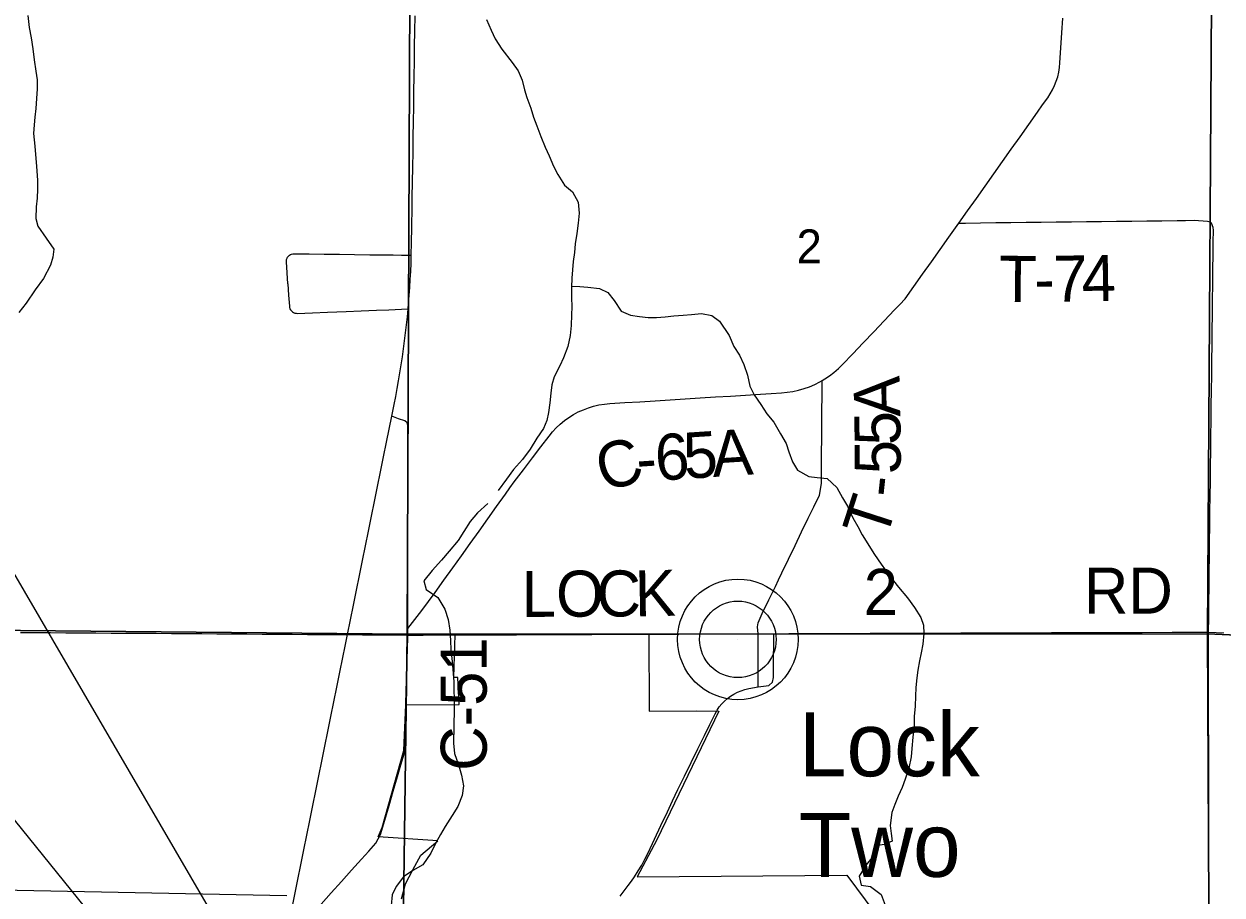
# Model space of a CAD drawing. Extents: x 0 to 34, y 0 to 22.
# Drawn here: x 5.324 to 6.802, y 18.119 to 19.194 of the extents above; entities that cross this region are included whole.
import ezdxf

# ---------------------------------------------------------------- set-up
doc = ezdxf.new("R2010")
doc.units = 0
for name, color, linetype in [('GM_X_Corporation', 7, 'Continuous'), ('GM_X_County_Road', 7, 'Continuous'), ('GM_X_County_Road_Text', 7, 'Continuous'), ('GM_X_Minor_River', 7, 'Continuous'), ('GM_X_Section_Text', 7, 'Continuous'), ('GM_X_State_Route', 7, 'Continuous'), ('GM_X_Township_Road', 7, 'Continuous'), ('GM_X_Township_Road_Text', 7, 'Continuous'), ('GM_X_Unincorporated', 7, 'Continuous'), ('GM_X_Unincorporated_Location', 7, 'Continuous'), ('GM_X_Unincorporated_Text', 7, 'Continuous'), ('SH_Text', 7, 'Continuous')]:
    doc.layers.add(name, color=color, linetype=linetype)

msp = doc.modelspace()

# ---------------------------------------------------------------- linework, layer by layer
at = {"layer": 'GM_X_Corporation'}
for points in [[(5.8008, 19.4289), (5.7966, 18.4409), (4.7982, 18.4503), (4.8082, 19.4446)], [(5.8008, 19.4289), (6.7907, 19.4159), (6.7843, 18.4413), (5.7966, 18.4409)], [(6.7967, 19.4154), (7.8071, 19.3973), (7.7914, 18.4475), (7.7907, 18.396), (6.7843, 18.4413), (6.7907, 19.4159)], [(5.7966, 18.4409), (5.7831, 17.4286), (4.7862, 17.4375), (4.7982, 18.4503)], [(5.7966, 18.4409), (6.7843, 18.4413), (6.7891, 17.4339), (5.7831, 17.4286)], [(7.7907, 18.396), (7.7756, 17.4406), (7.775, 17.3902), (6.7891, 17.4339), (6.7843, 18.4413)]]:
    msp.add_lwpolyline(points, close=True, dxfattribs=at)
for points in [[(5.7896, 18.1144), (5.7946, 18.133), (5.8037, 18.1501), (5.8135, 18.1683), (5.8344, 18.186), (5.761, 18.1909), (5.7658, 18.2026), (5.7926, 18.2977), (5.7951, 18.354), (5.7959, 18.354), (5.8607, 18.3543), (5.8593, 18.3874), (5.8544, 18.3874), (5.856, 18.4404), (6.095, 18.4413), (6.0953, 18.3461), (6.1536, 18.3463), (6.1813, 18.3461), (6.1047, 18.1874), (6.0806, 18.1418), (6.3391, 18.1436), (6.4654, 17.9737)], [(5.2945, 18.1254), (5.6481, 18.1185)]]:
    msp.add_lwpolyline(points, dxfattribs=at)
at = {"layer": 'GM_X_County_Road'}
msp.add_line((5.7977, 18.4399), (5.7977, 18.4479), dxfattribs=at)
for points in [[(6.4775, 18.9482), (6.4883, 18.9635), (6.4991, 18.9787), (6.5098, 18.9939), (6.5206, 19.0091), (6.5314, 19.0243), (6.5422, 19.0395), (6.553, 19.0547), (6.5637, 19.0699), (6.5745, 19.0851), (6.5808, 19.094), (6.5871, 19.1029), (6.5903, 19.1077), (6.5931, 19.1128), (6.5956, 19.118), (6.5977, 19.1234), (6.5995, 19.1289), (6.6008, 19.1345), (6.6018, 19.1403), (6.6023, 19.146), (6.6035, 19.1646), (6.6047, 19.1828), (6.6058, 19.2009)], [(5.7977, 18.4479), (5.8033, 18.4554), (5.8146, 18.4702), (5.8229, 18.4813), (5.8313, 18.4924), (5.8421, 18.5075), (5.853, 18.5227), (5.8638, 18.5379), (5.8746, 18.553), (5.8855, 18.5682), (5.8963, 18.5834), (5.9071, 18.5985), (5.918, 18.6137), (5.9234, 18.6214), (5.9289, 18.6291), (5.9402, 18.6439), (5.9515, 18.6587), (5.9616, 18.6721), (5.9718, 18.6855), (5.9761, 18.6907), (5.9807, 18.6956), (5.9856, 18.7003), (5.9908, 18.7046), (5.9962, 18.7085), (6.002, 18.7121), (6.0079, 18.7153), (6.0141, 18.718), (6.0204, 18.7204), (6.0268, 18.7224), (6.0334, 18.7239), (6.0401, 18.725), (6.0468, 18.7256), (6.0654, 18.7268), (6.084, 18.7279), (6.1026, 18.7291), (6.1212, 18.7302), (6.1398, 18.7314), (6.1584, 18.7325), (6.177, 18.7337), (6.1956, 18.7349), (6.2142, 18.736), (6.2328, 18.7372), (6.2458, 18.738), (6.2588, 18.7388), (6.2658, 18.7395), (6.2728, 18.7405), (6.2797, 18.7421), (6.2864, 18.744), (6.2931, 18.7464), (6.2996, 18.7492), (6.3059, 18.7523), (6.3088, 18.754), (6.312, 18.7559), (6.3178, 18.7598), (6.3234, 18.7641), (6.3288, 18.7687), (6.3338, 18.7737), (6.3467, 18.7871), (6.3595, 18.8006), (6.3724, 18.8141), (6.3853, 18.8276), (6.3982, 18.8411), (6.4047, 18.8479), (6.4112, 18.8547), (6.422, 18.8699), (6.4328, 18.8852), (6.4436, 18.9004), (6.4543, 18.9156), (6.4651, 18.9308), (6.4713, 18.9395), (6.4775, 18.9482)], [(5.7977, 18.4479), (5.7977, 18.6988), (5.7966, 18.7018), (5.7939, 18.7041), (5.7861, 18.7069), (5.7776, 18.71)], [(5.3194, 18.4432), (5.338, 18.443), (5.3567, 18.4429), (5.3753, 18.4428), (5.3939, 18.4427), (5.4126, 18.4426), (5.4312, 18.4424), (5.4499, 18.4423), (5.4685, 18.4422), (5.4871, 18.4421), (5.5058, 18.4419), (5.5244, 18.4418), (5.5431, 18.4417), (5.5617, 18.4416), (5.5804, 18.4414), (5.599, 18.4413), (5.6176, 18.4412), (5.6363, 18.441), (5.6549, 18.4409), (5.6736, 18.4408), (5.6922, 18.4407), (5.7075, 18.4406), (5.7229, 18.4405)], [(5.7229, 18.4405), (5.7415, 18.4403), (5.7602, 18.4402), (5.7788, 18.4401), (5.7977, 18.4399)], [(5.795, 18.3536), (5.7956, 18.3723), (5.7962, 18.3909), (5.7967, 18.4095), (5.7972, 18.4232), (5.7976, 18.4369), (5.7977, 18.4399)], [(5.7977, 18.4399), (5.8163, 18.44), (5.835, 18.4401), (5.8569, 18.4402)], [(5.8569, 18.4402), (5.8756, 18.4402), (5.8942, 18.4403), (5.9128, 18.4404), (5.9315, 18.4404), (5.9501, 18.4405), (5.9688, 18.4406), (5.9874, 18.4406), (6.0061, 18.4407), (6.0247, 18.4408), (6.0433, 18.4409), (6.062, 18.4409), (6.0784, 18.441), (6.0948, 18.4411)], [(6.0948, 18.4411), (6.1134, 18.4411), (6.132, 18.4412), (6.1507, 18.4413), (6.1693, 18.4413), (6.188, 18.4414), (6.2066, 18.4415), (6.23, 18.4416)], [(6.23, 18.4416), (6.249, 18.4416), (6.2677, 18.4417), (6.3122, 18.4419), (6.3308, 18.4419), (6.3495, 18.442), (6.3681, 18.4421), (6.3867, 18.4421), (6.4054, 18.4422), (6.424, 18.4423), (6.4427, 18.4423), (6.4613, 18.4424), (6.4799, 18.4425), (6.4986, 18.4426), (6.5172, 18.4426), (6.5359, 18.4427), (6.5545, 18.4428), (6.5731, 18.4428), (6.5918, 18.4429), (6.6291, 18.443), (6.6477, 18.4431), (6.6664, 18.4432), (6.7036, 18.4433), (6.7409, 18.4434), (6.7596, 18.4435), (6.7856, 18.4436)], [(6.7856, 18.4436), (6.8043, 18.4427)], [(5.7638, 18.1937), (5.769, 18.2116), (5.7743, 18.2295), (5.7795, 18.2474), (5.7847, 18.2653), (5.7889, 18.2799), (5.7932, 18.2946), (5.7938, 18.3132), (5.7943, 18.3318), (5.7947, 18.3427), (5.795, 18.3536)], [(5.6664, 18.081), (5.6781, 18.0942), (5.6906, 18.1081), (5.703, 18.1219), (5.7155, 18.1358), (5.7279, 18.1497), (5.7404, 18.1636), (5.7492, 18.1734), (5.758, 18.1833), (5.7638, 18.1937)]]:
    msp.add_lwpolyline(points, dxfattribs=at)
at = {"layer": 'GM_X_Minor_River'}
for points in [[(5.3287, 19.2045), (5.3303, 19.1896), (5.3327, 19.177), (5.3346, 19.1633), (5.3362, 19.1496), (5.3386, 19.1359), (5.3402, 19.1248), (5.34, 19.1138), (5.3393, 19.1021), (5.3383, 19.0895), (5.3373, 19.0789), (5.3363, 19.0695), (5.3357, 19.0588), (5.3372, 19.0432), (5.3381, 19.0329), (5.3393, 19.0185), (5.3404, 19.0006), (5.3406, 18.9903), (5.34, 18.979), (5.339, 18.9683), (5.3383, 18.9539), (5.3411, 18.9444), (5.351, 18.9297), (5.3605, 18.9162), (5.3596, 18.9063), (5.3567, 18.8965), (5.348, 18.88), (5.3378, 18.8658), (5.3264, 18.8493), (5.3174, 18.8378)], [(5.8946, 19.1993), (5.9004, 19.1863), (5.9051, 19.1755), (5.9135, 19.1628)], [(5.9135, 19.1628), (5.9262, 19.1464), (5.9335, 19.136), (5.9385, 19.1245), (5.9416, 19.1126), (5.9444, 19.1031), (5.9494, 19.09), (5.9525, 19.0789), (5.9568, 19.0682), (5.9618, 19.0552), (5.9671, 19.0421), (5.9718, 19.0314), (5.9771, 19.0183), (5.9825, 19.0083), (5.9909, 18.9952), (6.0009, 18.987), (6.0078, 18.9739), (6.009, 18.9606), (6.0079, 18.9481), (6.006, 18.9352), (6.0042, 18.9227), (6.0031, 18.9121), (6.0017, 18.9008), (6.0007, 18.8906), (6, 18.8803), (5.9994, 18.8693), (5.9994, 18.8564), (5.9999, 18.845), (5.9996, 18.8352), (5.9989, 18.8219), (5.9978, 18.8094), (5.9951, 18.7958), (5.9898, 18.7819), (5.985, 18.7721), (5.9782, 18.7587), (5.9753, 18.7485), (5.9739, 18.7383), (5.9728, 18.7265), (5.971, 18.7144), (5.9692, 18.7046), (5.9648, 18.6948), (5.9565, 18.6829), (5.9486, 18.6691), (5.9391, 18.6564), (5.9278, 18.6442), (5.9192, 18.6323), (5.9089, 18.6185)], [(5.9994, 18.8703), (6.0096, 18.8702), (6.0198, 18.8692), (6.0342, 18.8677), (6.0443, 18.8625), (6.052, 18.8528), (6.0608, 18.8396), (6.0724, 18.8348), (6.0834, 18.833), (6.094, 18.8319), (6.1042, 18.8317), (6.1149, 18.8325), (6.1259, 18.8338), (6.1373, 18.8346), (6.1476, 18.8355), (6.1601, 18.8367), (6.1726, 18.8341), (6.1823, 18.8273), (6.1939, 18.8096), (6.1996, 18.7961), (6.2066, 18.7853), (6.212, 18.7738), (6.2165, 18.7608), (6.2196, 18.747), (6.225, 18.7363), (6.233, 18.7243), (6.2407, 18.7127), (6.2492, 18.7026), (6.2575, 18.6883), (6.2644, 18.6764), (6.2676, 18.6661), (6.2722, 18.6538), (6.2783, 18.6434), (6.2925, 18.6354), (6.3028, 18.6344), (6.3149, 18.6333), (6.3267, 18.622), (6.334, 18.6093), (6.3402, 18.5988), (6.3466, 18.5846), (6.3528, 18.5738), (6.3582, 18.5638), (6.3735, 18.5395), (6.3815, 18.5275), (6.3922, 18.5128), (6.4028, 18.4992), (6.4142, 18.486), (6.4226, 18.474), (6.4307, 18.4617), (6.4338, 18.4521), (6.4343, 18.4418), (6.4332, 18.4286), (6.431, 18.418), (6.4289, 18.4082), (6.4267, 18.3968), (6.4257, 18.387), (6.4246, 18.3752), (6.424, 18.3646), (6.4236, 18.3521), (6.4225, 18.3396), (6.4223, 18.3293), (6.4207, 18.3138), (6.4196, 18.2998), (6.4186, 18.2896), (6.4159, 18.2756), (6.4114, 18.262), (6.4074, 18.2519), (6.4025, 18.241), (6.3985, 18.2308), (6.3948, 18.221), (6.3929, 18.2048), (6.3938, 18.1952), (6.395, 18.1857), (6.3854, 18.1814), (6.3732, 18.1794), (6.3718, 18.1673), (6.3632, 18.1565), (6.3544, 18.1423), (6.3568, 18.1312), (6.3685, 18.1298), (6.3816, 18.12), (6.3865, 18.1065)], [(5.8963, 18.6021), (5.8835, 18.5906), (5.8746, 18.5801), (5.8667, 18.5678), (5.8596, 18.5565), (5.8487, 18.5435), (5.839, 18.5323), (5.8277, 18.5197), (5.8172, 18.507), (5.82, 18.4963), (5.8346, 18.4864), (5.8433, 18.4718), (5.8472, 18.4592), (5.8492, 18.4458), (5.8501, 18.4332), (5.8506, 18.4218), (5.8521, 18.4074), (5.8533, 18.3925), (5.8542, 18.3822), (5.8544, 18.3719), (5.8545, 18.3613), (5.8546, 18.3484), (5.8537, 18.3066), (5.8549, 18.294), (5.8603, 18.2787), (5.8638, 18.2672), (5.8662, 18.2538), (5.8644, 18.2421), (5.8592, 18.2285), (5.8521, 18.2173), (5.8435, 18.2038), (5.8379, 18.194), (5.832, 18.1835), (5.8257, 18.1707), (5.8159, 18.1565), (5.8036, 18.1496), (5.792, 18.1415), (5.783, 18.1295), (5.7782, 18.1194), (5.7768, 18.1061)]]:
    msp.add_lwpolyline(points, dxfattribs=at)
at = {"layer": 'GM_X_State_Route'}
for points in [[(5.8026, 18.9497), (5.8028, 18.9615), (5.803, 18.9801), (5.8033, 18.9988), (5.8036, 19.0174), (5.8039, 19.0361), (5.8042, 19.0547), (5.8044, 19.0733), (5.8047, 19.092), (5.805, 19.1106), (5.8053, 19.1293), (5.8056, 19.1479), (5.8058, 19.1666), (5.8061, 19.1852), (5.8064, 19.2038)], [(5.7229, 18.4405), (5.7266, 18.4587), (5.7303, 18.477), (5.734, 18.4953), (5.7377, 18.5135), (5.7414, 18.5318), (5.7451, 18.5501), (5.7489, 18.5683), (5.7526, 18.5866), (5.7563, 18.6049), (5.76, 18.6231), (5.7637, 18.6414), (5.7674, 18.6597), (5.7711, 18.6779), (5.7744, 18.694), (5.7776, 18.71), (5.7806, 18.7246), (5.7825, 18.7343), (5.7844, 18.7441), (5.7861, 18.7538), (5.7878, 18.7636), (5.7893, 18.7734), (5.7908, 18.7832), (5.7922, 18.793), (5.7935, 18.8029), (5.7947, 18.8127), (5.7959, 18.8226), (5.7969, 18.8325), (5.7979, 18.8423), (5.7984, 18.849), (5.7992, 18.8589), (5.7999, 18.8688), (5.8005, 18.8788), (5.8011, 18.8887), (5.8015, 18.8986), (5.8018, 18.9086), (5.8022, 18.9242), (5.8025, 18.9429), (5.8026, 18.9497)], [(5.6456, 18.058), (5.6493, 18.0763), (5.653, 18.0946), (5.6556, 18.1073), (5.6581, 18.12), (5.6618, 18.1382), (5.6655, 18.1565), (5.6692, 18.1748), (5.6729, 18.1931), (5.6766, 18.2113), (5.6803, 18.2296), (5.684, 18.2479), (5.6877, 18.2662), (5.6913, 18.2844), (5.695, 18.3027), (5.6987, 18.321), (5.7024, 18.3393), (5.7061, 18.3575), (5.7098, 18.3758), (5.7135, 18.3941), (5.7172, 18.4123), (5.72, 18.4264), (5.7229, 18.4405)]]:
    msp.add_lwpolyline(points, dxfattribs=at)
at = {"layer": 'GM_X_Township_Road'}
for points in [[(6.4775, 18.9482), (6.4858, 18.9483), (6.5044, 18.9486), (6.5231, 18.9488), (6.5417, 18.949), (6.5604, 18.9492), (6.579, 18.9495), (6.5976, 18.9497), (6.6163, 18.9499), (6.6349, 18.9501), (6.6536, 18.9503), (6.6722, 18.9506), (6.6908, 18.9508), (6.7095, 18.951), (6.7281, 18.9512), (6.7468, 18.9514), (6.7573, 18.9516), (6.7678, 18.9517), (6.7845, 18.9508), (6.7877, 18.9496), (6.7893, 18.948)], [(6.7871, 17.4313), (6.7856, 18.4436), (6.7859, 18.4622), (6.7861, 18.4809), (6.7863, 18.4995), (6.7865, 18.5181), (6.7868, 18.5368), (6.787, 18.5554), (6.7872, 18.5741), (6.7874, 18.5927), (6.7877, 18.6113), (6.7879, 18.63), (6.7881, 18.6486), (6.7884, 18.6673), (6.7886, 18.6859), (6.7888, 18.7045), (6.789, 18.7232), (6.7893, 18.7418), (6.7895, 18.7605), (6.7897, 18.7791), (6.7899, 18.7978), (6.7902, 18.8164), (6.7904, 18.835), (6.7906, 18.8537), (6.7908, 18.8723), (6.7911, 18.891), (6.7913, 18.9096), (6.7915, 18.9246), (6.7917, 18.9396), (6.7913, 18.9429), (6.7893, 18.948)], [(5.6494, 18.8732), (5.6485, 18.8868), (5.6476, 18.9004), (5.6479, 18.9035), (5.6484, 18.9049), (5.6492, 18.9063), (5.6502, 18.9075), (5.6513, 18.9086), (5.6526, 18.9094), (5.6541, 18.91), (5.6556, 18.9104), (5.6572, 18.9105), (5.6758, 18.9102), (5.6944, 18.91), (5.7131, 18.9097), (5.7317, 18.9095), (5.7504, 18.9092), (5.769, 18.909), (5.7793, 18.9089), (5.7896, 18.9087), (5.8018, 18.9086)], [(5.6494, 18.8732), (5.6503, 18.8595), (5.6513, 18.8457), (5.6515, 18.8441), (5.652, 18.8426), (5.6528, 18.8412), (5.6538, 18.8399), (5.655, 18.8388), (5.6564, 18.8379), (5.6579, 18.8373), (5.6595, 18.837), (5.6611, 18.8369), (5.6797, 18.8376), (5.6983, 18.8384), (5.7099, 18.8388), (5.7214, 18.8393), (5.74, 18.84), (5.7587, 18.8408), (5.7742, 18.8414), (5.7897, 18.842), (5.7979, 18.8423)], [(6.2549, 18.508), (6.2592, 18.5168), (6.2673, 18.5336), (6.2754, 18.5504), (6.2835, 18.5672), (6.2916, 18.584), (6.2985, 18.5982), (6.3054, 18.6125), (6.3078, 18.6271), (6.308, 18.6457), (6.3081, 18.6643), (6.3082, 18.683), (6.3084, 18.7016), (6.3085, 18.7203), (6.3086, 18.7315), (6.3087, 18.7427), (6.3088, 18.754)], [(6.2298, 18.3848), (6.2298, 18.3946), (6.2299, 18.4133), (6.23, 18.4416), (6.229, 18.45), (6.2298, 18.4552), (6.2349, 18.4664), (6.243, 18.4832), (6.2511, 18.5), (6.2549, 18.508)], [(6.2297, 18.376), (6.243, 18.3777), (6.2476, 18.3819), (6.2488, 18.3876), (6.2489, 18.4063), (6.249, 18.4338), (6.249, 18.4416)], [(6.1785, 18.3458), (6.1792, 18.3471), (6.1819, 18.3512), (6.1849, 18.355), (6.1883, 18.3585), (6.1919, 18.3618), (6.1958, 18.3647), (6.1999, 18.3672), (6.2043, 18.3695), (6.2088, 18.3713), (6.2135, 18.3727), (6.2182, 18.3738), (6.2297, 18.376), (6.2298, 18.3848)], [(6.0772, 18.1417), (6.0818, 18.1489), (6.0861, 18.1562), (6.0901, 18.1636), (6.0939, 18.1712), (6.1019, 18.1881), (6.1099, 18.2049), (6.1178, 18.2218), (6.1243, 18.2355), (6.1308, 18.2492), (6.1391, 18.2659), (6.1473, 18.2826), (6.1555, 18.2994), (6.1637, 18.3161), (6.1703, 18.3295), (6.1769, 18.3428), (6.1785, 18.3458)], [(6.0597, 18.1178), (6.0694, 18.1308), (6.0734, 18.1362), (6.0772, 18.1417)]]:
    msp.add_lwpolyline(points, dxfattribs=at)
at = {"layer": 'GM_X_Unincorporated'}
for radius in [0.0744, 0.0472]:
    msp.add_circle((6.2048, 18.4346), radius, dxfattribs=at)
at = {"layer": 'GM_X_Unincorporated_Location'}
msp.add_line((6.2048, 18.4346), (6.2048, 18.4346), dxfattribs=at)
at = {"layer": 'SH_Text'}
msp.add_lwpolyline([(5.9461, 17.427), (4.7562, 19.4692), (4.7562, 18.8986)], close=True, dxfattribs=at)

# ---------------------------------------------------------------- texts
at = {"layer": 'GM_X_County_Road_Text'}
for s, height, rotation, p in [('6', 0.0568, 3.733, (6.1043, 18.6303)), ('5', 0.0568, 3.7395, (6.1393, 18.6326)), ('A', 0.0568, 3.7365, (6.1742, 18.6349)), ('C', 0.0568, 16.6204, (6.0396, 18.6161)), ('-', 0.0568, 3.7261, (6.081, 18.6288)), ('L', 0.0568, 0.2636, (5.938, 18.4623)), ('O', 0.0568, 0.2656, (5.9805, 18.4625)), ('C', 0.0568, 0.2693, (6.0305, 18.4627)), ('K', 0.0568, 1.0083, (6.078, 18.4629)), ('2', 0.0568, 0, (6.3601, 18.4648)), ('RD', 0.05682, 0, (6.6318, 18.4664)), ('C-51', 0.05682, 90.0982, (5.895, 18.2725))]:
    msp.add_text(s, height=height, rotation=rotation, dxfattribs=at).set_placement(p)
at = {"layer": 'GM_X_Section_Text'}
msp.add_text('2', height=0.0419, rotation=0, dxfattribs=at).set_placement((6.2772, 18.8986))
at = {"layer": 'GM_X_Township_Road_Text'}
for s, rotation, p in [('T', 359.3721, (6.5269, 18.8513)), ('7', 0.8208, (6.5943, 18.8511)), ('4', 0.9117, (6.6294, 18.8516)), ('-', 0.4819, (6.5706, 18.8509)), ('A', 91.1595, (6.4052, 18.7096)), ('5', 91.0313, (6.4058, 18.6745)), ('5', 89.8892, (6.4057, 18.6383)), ('-', 83.8877, (6.4029, 18.6086)), ('T', 72.0848, (6.3872, 18.5557))]:
    msp.add_text(s, height=0.0568, rotation=rotation, dxfattribs=at).set_placement(p)
at = {"layer": 'GM_X_Unincorporated_Text'}
for s, p in [('Lock', (6.2801, 18.2657)), ('Two', (6.2801, 18.1416))]:
    msp.add_text(s, height=0.07898, rotation=0, dxfattribs=at).set_placement(p)

doc.saveas('drawing.dxf')
